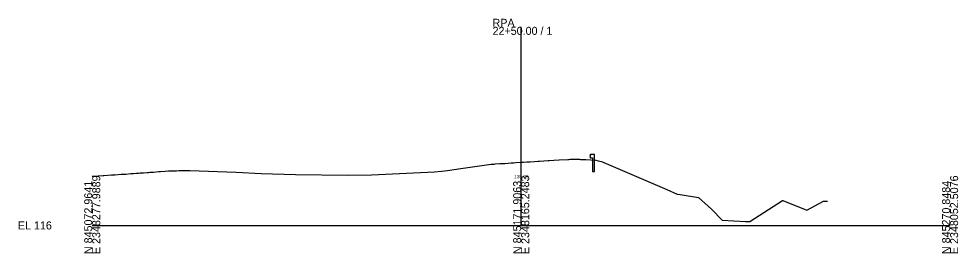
# Model space of a CAD drawing. Extents: x -76 to 2348158, y -10 to 845166.
# Drawn here: x -75.7 to 252.8, y -9.7 to 72.2 of the extents above; entities that cross this region are included whole.
import ezdxf

# ---------------------------------------------------------------- set-up
doc = ezdxf.new("R2010")
doc.units = 0
for name, color, linetype in [('Default', 7, 'Continuous'), ('Exist Cross Section Cell', 7, 'Continuous'), ('Exist XS Center Line Elevation Label', 7, 'Continuous'), ('Exist XS Ground Line', 7, 'Continuous'), ('Prop CMT Guardrail Graphics', 7, 'Continuous')]:
    doc.layers.add(name, color=color, linetype=linetype)

msp = doc.modelspace()

# ---------------------------------------------------------------- linework, layer by layer
at = {"layer": 'Exist Cross Section Cell'}
for p, q in [((100, 0), (100, 69.44)), ((-50, 0), (100, 0)), ((100, 0), (250, 0))]:
    msp.add_line(p, q, dxfattribs=at)
at = {"layer": 'Exist XS Ground Line'}
msp.add_lwpolyline([(-50, 17.26), (-49.68, 17.28), (-46.24, 17.49), (-45.9, 17.52), (-43.22, 17.68), (-42.08, 17.75), (-39.91, 17.89), (-39.15, 17.93), (-38.3, 17.99), (-36.56, 18.11), (-35.6, 18.18), (-34.51, 18.25), (-33.84, 18.3), (-33.24, 18.35), (-32.08, 18.43), (-30.77, 18.53), (-30.3, 18.56), (-29.9, 18.59), (-28.53, 18.69), (-26.72, 18.82), (-26.11, 18.87), (-24.49, 18.97), (-23.3, 19.06), (-22.04, 19.09), (-20.5, 19.14), (-19.78, 19.16), (-19.41, 19.17), (-16.33, 19.21), (-15.89, 19.2), (0.35, 18.64), (9.09, 18.21), (21.1, 17.84), (39.41, 17.56), (47.71, 17.68), (69.73, 18.72), (72.17, 18.97), (74.21, 19.27), (78.9, 19.92), (89.55, 21.41), (90.14, 21.45), (90.54, 21.47), (90.88, 21.5), (92.52, 21.62), (93.14, 21.65), (94.34, 21.72), (95.5, 21.79), (96.51, 21.86), (97.27, 21.91), (98.15, 21.97), (100, 22.09), (100.81, 22.14), (101.94, 22.21), (103.11, 22.28), (104.64, 22.38), (105.89, 22.43), (106.45, 22.46), (109.47, 22.66), (109.78, 22.68), (111.39, 22.78), (113.3, 22.89), (116.36, 23.07), (116.69, 23.09), (117.13, 23.14), (117.52, 23.15), (119.92, 23.13), (120.45, 23.12), (120.75, 23.1), (122.6, 23.05), (126.09, 22.86), (126.97, 22.64), (128.09, 22.37), (150.89, 12.52), (154.51, 10.97), (155.61, 10.79), (161.96, 9.77), (166.56, 5.73), (170.34, 1.8), (178.49, 1.41), (179.94, 1.36), (191.4, 8.78), (191.5, 8.78), (199.93, 5.39), (205.77, 8.45), (206.57, 8.51), (207.08, 8.5)], dxfattribs=at)
at = {"layer": 'Prop CMT Guardrail Graphics'}
for p, q in [((124.27, 24.85), (124, 24.56)), ((124, 24.56), (124.27, 24.27)), ((124.27, 24.27), (124, 23.98)), ((124, 23.98), (124.27, 23.69)), ((125.6, 24.85), (124.27, 24.85)), ((124.27, 23.69), (124.94, 23.69)), ((124.94, 23.69), (124.94, 18.85)), ((125.6, 18.85), (125.6, 24.85)), ((124.94, 18.85), (125.6, 18.85))]:
    msp.add_line(p, q, dxfattribs=at)

# ---------------------------------------------------------------- texts
at = {"layer": 'Default'}
msp.add_text('-', height=0.0001, dxfattribs=at).set_placement((-50, 0))
at = {"layer": 'Exist Cross Section Cell'}
for s, p in [('22+50.00 / 1', (90, 66.64)), ('RPA', (90, 69.44)), ('EL 116', (-76, -1.4))]:
    msp.add_text(s, height=2.8, dxfattribs=at).set_placement(p)
for s, p in [('E 2348277.9889', (-47.2, -10)), ('E 2348165.2483', (102.8, -10)), ('E 2348052.5076', (252.8, -10)), ('N 845072.9641', (-50, -10)), ('N 845171.9063', (100, -10)), ('N 845270.8484', (250, -10))]:
    msp.add_text(s, height=2.8, rotation=90, dxfattribs=at).set_placement(p)
at = {"layer": 'Exist XS Center Line Elevation Label'}
msp.add_text('138.09', height=1.2, dxfattribs=at).set_placement((97.51, 16.49))

doc.saveas('drawing.dxf')
